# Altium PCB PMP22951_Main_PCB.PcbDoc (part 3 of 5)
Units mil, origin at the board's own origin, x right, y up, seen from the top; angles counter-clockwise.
Board outline 6643.5 x 4153.54 mil, 6 copper layers (Top Layer, Signal Layer 1, Signal Layer 2, Signal Layer 3, Signal Layer 4, Bottom Layer), stack 65.8 mil thick; 139 components, 80 nets, 687 pads, 417 vias.
Unrouted connection lines stored in the file: 2.
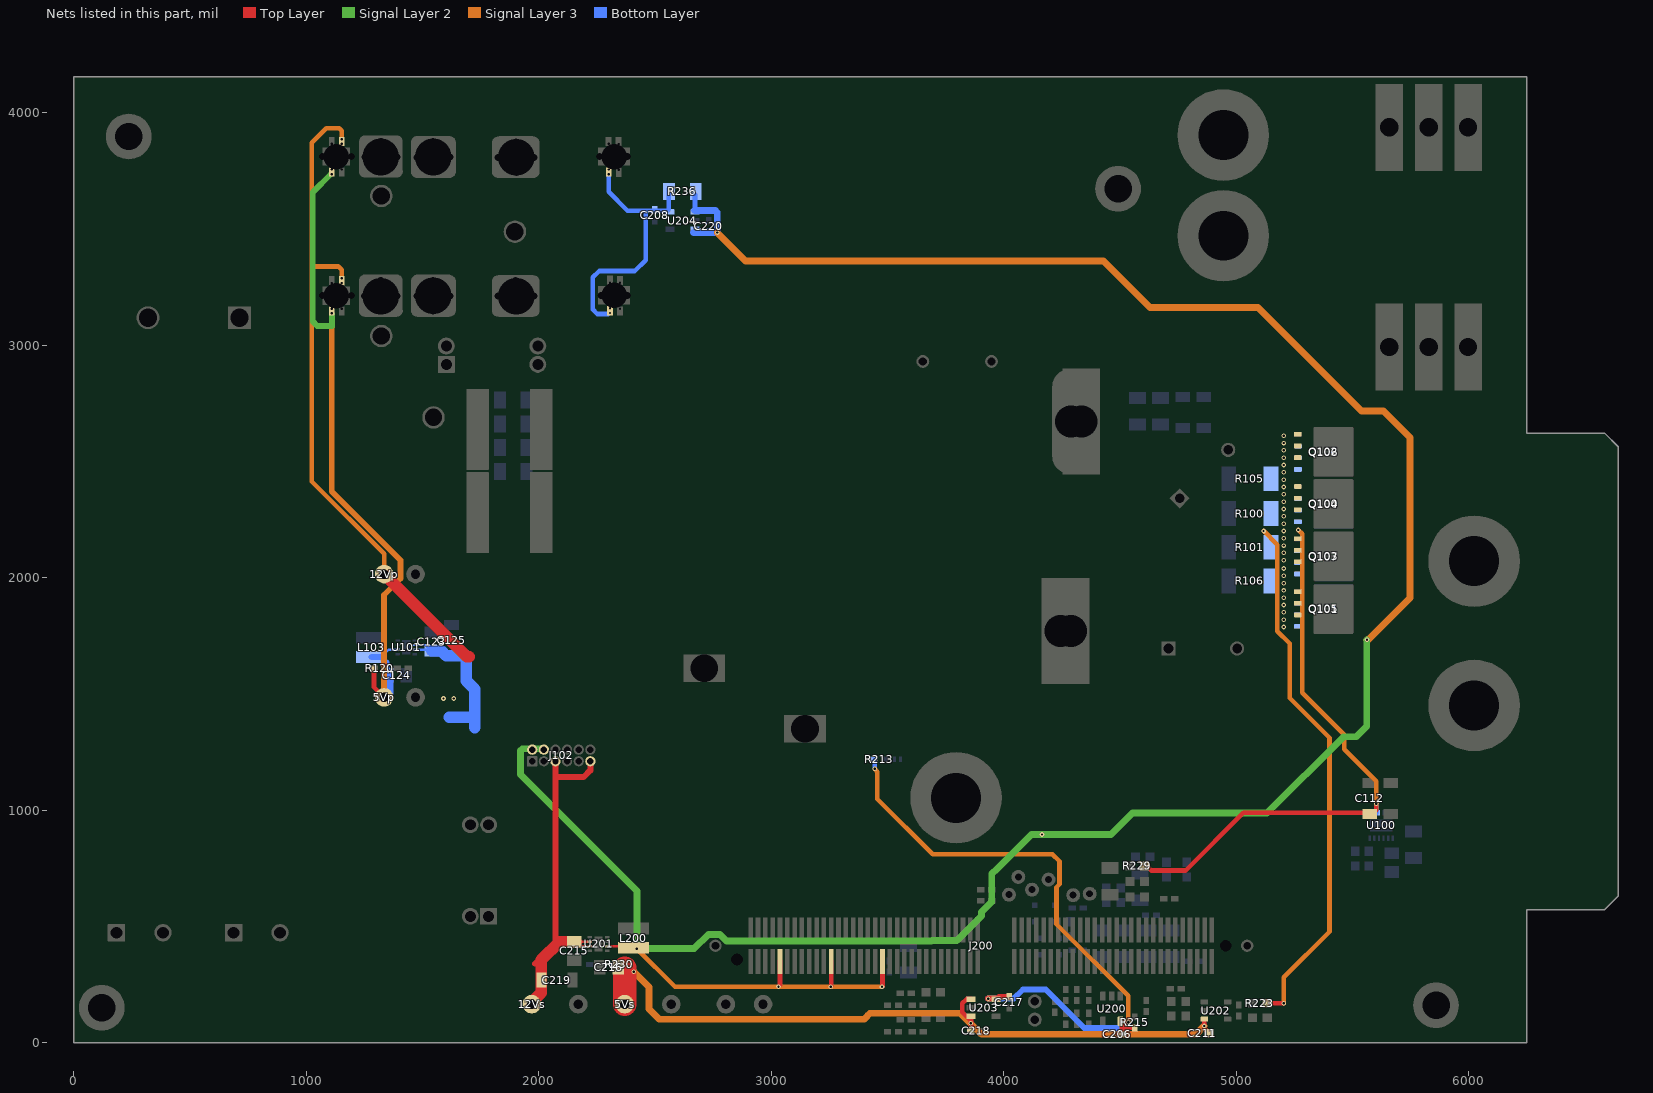
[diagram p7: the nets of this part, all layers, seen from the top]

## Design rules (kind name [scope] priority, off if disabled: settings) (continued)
SilkToSilkClearance SilkToSilkClearance_Pb-FreeLogo [(HasFootprint('Pb-Free_Overlay_Medium') OR HasFootprint('Pb-Free_Overlay_Small')) vs (HasFootprint('Pb-Free_Overlay_Medium') OR HasFootprint('Pb-Free_Overlay_Small'))] p1: silktosilkclearance=0
SilkToSilkClearance [All] p2: silktosilkclearance=4
SilkToSolderMaskClearance SilkToComponentPadClearance [(IsPad or IsFill or IsRegion) and InAnycomponent] p1: minsilkscreentomaskgap=5 clearancetoexposedcopper=TRUE
SilkToSolderMaskClearance "Silk to Solder Mask Opening" [All] p2: minsilkscreentomaskgap=4 clearancetoexposedcopper=FALSE
SolderMaskExpansion [All] p1: expansion=1.97
Width [All] p1: maxlimit=100 minlimit=6 preferedwidth=10 checkconnectedcopper=TRUE
13 further rules are at their usual default settings.

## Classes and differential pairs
component class PMP22951_Main_PSFB: 5Vp 12Vp C100 C101 C102 C103 C104 C105 C106 C110 C111 C112 C113 C114 C115 C116 C117 C118 C123 C124 C125 C224 C226 C242 C243 C244 CT100 CT101 CT200 J102 L100 L103 LOGO100 LOGO101 Logo102 Logo103 PGND Q100 Q101 Q102 Q103 Q104 Q105 Q106 Q107 Q215 Q216 Q217 Q218 Q219 R100 R101 R102 R103 R104 R105 R106 R107 R108 R116 R120 R121 SGND TP100 TP108 TP109 TP110 TP217 TP218 TP219 TP220 TP221 TP222 U100 U101 Vin Vout+ Vout-
component class PMP22951_Main_Controller: 5Vs 12Vs C200 C201 C202 C203 C204 C205 C206 C207 C208 C209 C210 C211 C212 C213 C214 C215 C216 C217 C218 C219 C220 C311 C333 D200 D201 D202 D203 J200 J300 J305 J306 L200 PSON R200 R201 R202 R203 R204 R205 R206 R207 R208 R209 R210 R211 R212 R213 R214 R215 R216 R217 R218 R219 R220 R221 R222 R223 R224 R225 R226 R227 R228 R229 R230 R231 R232 R233 R234 R235 R236 R305 R323 R329 R331 R333 R334 R335 R337 RT200 SGND U200 U201 U202 U203 U204
net class HV: NetT100_1 SWNODE2 VBB

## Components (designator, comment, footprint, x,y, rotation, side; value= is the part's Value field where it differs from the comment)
5Vp "5000" Keystone5000 1335,1485 r180 bottom
5Vs "5000" Keystone5000 2370,165 r90 top
12Vp "5000" Keystone5000 1335,2015 r180 bottom
12Vs "5000" Keystone5000 1970,165 r90 top
C100 "450HXG220MEFCSN25X40" HXG_2500x4000 515.75,3118.11 r180 top value=220uF
C101 "CL31B223KHHNNNE" 1206 1889.76,2763.78 r0 bottom value=0.022uF
C102 "CL31B223KHHNNNE" 1206 1889.76,2456.69 r0 bottom value=0.022uF
C103 "CL31B223KHHNNNE" 1206 1889.76,2559.06 r0 bottom value=0.022uF
C104 "CL31B223KHHNNNE" 1206 1889.76,2661.42 r0 bottom value=0.022uF
C105 "B58031U5105M062" FP-B58031U5105M062_SMD2-MFG 1874.02,2279.53 r180 top value=1µF
C106 "B58031U5105M062" FP-B58031U5105M062_SMD2-MFG 1874.02,2637.8 r180 top value=1µF
C110 "70RXA1000M18X25" HE_1800x2500 4856.5,1695 r0 top value=1000uF
C111 "70RXA1000M18X25" HE_1800x2500 4861.5,2445 r45 top value=1000uF
C112 "GCM31CR72A105KA03" 1206_180 5575,1050 r270 top value=1uF
C113 "GCM31CR72A105KA03" 1206_180 5665,1050 r90 top value=1uF
C114 "C0805C104K1RACTU" 0805_HV 5669.29,773.74 r90 bottom value=0.1uF
C115 "06033C104JAT2A" 0603 5570.87,791.34 r90 bottom value=0.1uF
C116 "DE6E3KJ222MN3A" E_900x700x900 3800,2930 r0 bottom value=2200pF
C117 "GCM31CR72A105KA03" 1206_180 4860,2710 r90 bottom value=1uF
C118 "GCM31CR72A105KA03" 1206_180 4770,2710 r90 bottom value=1uF
C123 "C0805C105K3RACTU" 0805_HV 1540,1725 r90 bottom value=1uF
C124 "CL21A226KQQNNNE" 0805_HV 1390,1580 r0 bottom value=22uF
C125 "GCM31CR71C106KA64L" 1206_180 1625,1730 r90 bottom value=10uF
C200 "GRM155R70J103KA01D" 0402 3578.74,98.43 r180 top value=0.01uF
C201 "GRM155R70J103KA01D" 0402 3578.74,212.6 r180 top value=0.01uF
C202 "885012205044" 0402 4712.6,618.11 r0 top value=1000pF
C203 "GRM155R70J103KA01D" 0402 3925.2,610.24 r0 top value=0.01uF
C204 "GRM1555C1H2R2BA01D" 0402 4366.14,102.36 r270 top value=2.2pF
C205 "CGA2B2X7R1H471K050BA" 0402 4820,350 r0 bottom value=470pF
C206 "0402YC104KAT2A" 0402 4488.19,35.43 r180 top value=0.1uF
C207 "CGA2B2X7R1H222K050BA" 0402 4267.72,204.72 r90 top value=2200pF
C208 "GRM155R70J104KA01D" 0402 2500,3559.06 r270 bottom value=0.1uF
C209 "0402YC104KAT2A" 0402 4314.96,204.72 r270 top value=0.1uF
C210 "06035A102KAT2A" 0603 4503.94,633.86 r90 bottom value=1000pF
C211 "C1608X7R1E105K080AB" 0603 4854.33,39.37 r0 top value=1uF
C212 "GRM1555C1E4R7CA01D" 0402 5011.81,137.8 r270 top value=4.7pF
C213 "0402YC101KAT2A" 0402 4740.16,232.28 r180 top value=100pF
C214 "06035A102KAT2A" 0603 4574.8,625.98 r0 top value=1000pF
C215 "C0805C105K3RACTU" 0805_HV 2152.17,393.94 r270 top value=1uF
C216 "CL21A226KQQNNNE" 0805_HV 2302.17,323.94 r180 top value=22uF
C217 "GRM155R70J104KA01D" 0402 4023.62,173.23 r270 top value=0.1uF
C218 "GRM155R70J104KA01D" 0402 3881.89,51.18 r0 top value=0.1uF
C219 "GCM31CR71C106KA64L" 1206_180 2078.31,268.78 r0 top value=10uF
C220 "GRM155R70J104KA01D" 0402 2732.28,3511.81 r90 bottom value=0.1uF
CT100 "PAS6282NL" FP-PAS6282NL_PTH_12MM5_4MM5-MFG 1745,740 r270 top value=3.3mH
CT101 "PAS6282NL" FP-PAS6282NL_PTH_12MM5_4MM5-MFG 1799.21,2956.69 r180 top value=3.3mH
D200 "BAS316,115" SOD-323 4177.17,590.55 r180 bottom value=100V
D201 "BAS316,115" SOD-323 4177.17,519.68 r180 bottom value=100V
D202 "BAS316,115" SOD-323 4196.85,377.95 r0 bottom value=100V
D203 "BAS316,115" SOD-323 4196.85,448.82 r0 bottom value=100V
J102 "M50-3000645" FP-M50-3000645_HDR12-MFG 2097.05,1235 r0 top locked
J200 "HSEC8-160-01-L-DV-A-BL" controlCARD-120HSEC 3976.38,417.32 r180 top
L100 "PAL6431.392NL" FP-PAL6567.421NL_PTH_IND_34MM0_9MM5-MFG 4289.06,2221.06 r90 top value=3.9µH
L103 "74438336022" FP-74438336010_SMD2-MFG 1280,1700 r270 bottom
L200 "74438336022" FP-74438336010_SMD2-MFG 2407.17,448.94 r270 top
LOGO100 "CAUTION HOT SURFACE" IEC_HotSurface_Small 735,865 r0 top
LOGO101 "DANGER HIGH VOLTAGE" IEC_HighVoltage_Small 445,860 r0 top
Logo102 "FCC disclaimer" FCC_disclaimer 7751.97,7307.09 r90 top
Logo103 "WEEE logo" WEEE_Minimum 175,885 r0 top
PGND "5001" Keystone5001 1470,2015 r90 bottom
PGND "5001" Keystone5001 1470,1485 r90 bottom
PGND "1715721" PhoenixContact_1715721 283.46,472.44 r0 top
PSON "5003" Keystone5003 2805,165 r90 top
Q100 "CSD19502Q5B" DNK0008A#1 5375.98,2316.93 r0 top value=80V
Q101 "CSD19502Q5B" DNK0008A#1 5375.98,1864.17 r0 top value=80V
Q102 "CSD19502Q5B" DNK0008A#1 5375.98,2541.34 r0 top value=80V
Q103 "CSD19502Q5B" DNK0008A#1 5375.98,2092.52 r0 top value=80V
Q104 "CSD19502Q5B" DNK0008A#2 5376.97,2315.32 r0 bottom value=80V
Q105 "CSD19502Q5B" DNK0008A#2 5376.97,1865.32 r0 bottom value=80V
Q106 "CSD19502Q5B" DNK0008A#2 5376.97,2540.32 r0 bottom value=80V
Q107 "CSD19502Q5B" DNK0008A#2 5376.97,2090.32 r0 bottom value=80V
R100 "PMR50HZPFV2L00" 2010 5059.33,2275.63 r0 bottom value=0.002
R101 "PMR50HZPFV2L00" 2010 5059.33,2130.63 r0 bottom value=0.002
R102 "CRCW0603243RFKEA" 0603 4700.79,744.09 r270 bottom value=243
R103 "RC1206FR-079K76L" 1206 4675,2715 r270 bottom value=9.76k
R104 "RC1206FR-079K76L" 1206 4575,2715 r270 bottom value=9.76k
R105 "PMR50HZPFV2L00" 2010 5059.33,2425.63 r0 bottom value=0.002
R106 "PMR50HZPFV2L00" 2010 5059.33,1985.63 r0 bottom value=0.002
R107 "CRCW0603243RFKEA" 0603 4787.4,744.09 r270 bottom value=243
R108 "CRCW120647R0JNEA" 1206 5763.78,850.39 r90 bottom value=47
R116 "CRCW06030000Z0EA" 0603 5511.81,791.34 r270 bottom value=0
R120 "CRCW0402681KFKED" 0402 1315,1610 r180 top value=681k
R121 "CRCW0402130KFKED" 0402 1415,1610 r180 top value=130k
R200 "CRCW04024K99FKED" 0402 3629.92,47.24 r0 top value=4.99k
R201 "CRCW0603100RFKEA" 0603 3696.85,106.3 r180 top value=100
R202 "CRCW04029K31FKED" 0402 3523.62,47.24 r0 top value=9.31k
R203 "CRCW04024K99FKED" 0402 3629.92,161.42 r0 top value=4.99k
R204 "CRCW0603100RFKEA" 0603 3696.85,216.54 r180 top value=100
R205 "CRCW04020000Z0ED" 0402 4633.86,547.24 r0 bottom value=0
R206 "CRCW04020000Z0ED" 0402 4318.9,578.74 r0 bottom value=0
R207 "CRCW04029K31FKED" 0402 3523.62,161.42 r0 top value=9.31k
R208 "CRCW120614R7FKEA" 1206 4520,425 r90 bottom value=14.7
R209 "CRCW120614R7FKEA" 1206 4420,425 r90 bottom value=14.7
R210 "RC0603FR-079K76L" 0603 4287.4,488.19 r270 bottom value=9.76k
R211 "CRCW04021K40FKED" 0402 3925.2,657.48 r180 top value=1.40k
R212 "CRCW04020000Z0ED" 0402 4318.9,397.64 r0 bottom value=0
R213 "CRCW040210K0FKED" 0402 3464.92,1218.62 r0 bottom value=10.0k
R214 "CRCW04023K65FKED" 0402 4314.96,102.36 r90 top value=3.65k
R215 "CRCW040210K0FKED" 0402 4562.99,86.61 r270 top value=10.0k
R216 "CRCW04021K00FKED" 0402 4267.72,102.36 r270 top value=1.00k
R217 "CRCW04021K00FKED" 0402 4220.47,153.54 r270 top value=1.00k
R218 "RC0402FR-0756R2L" 0402 4614.17,157.48 r90 top value=56.2
R219 "CRCW040210K0FKED" 0402 4366.14,204.72 r90 top value=10.0k
R220 "CRCW120637K4FKEA" 1206 4586.61,669.29 r90 bottom value=37.4k
R221 "CRCW0603100RFKEA" 0603 4598.43,799.21 r0 bottom value=100
R222 "RC0603FR-071K82L" 0603 4440.94,633.86 r270 bottom value=1.82k
R223 "RC0603FR-074R75L" 0603 5102.36,169.29 r180 top value=4.75
R224 "RC0603FR-0724KL" 0603 4783.46,145.67 r270 top value=24.0k
R225 "CRCW120610K0FKEA" 1206 3590.55,358.27 r270 bottom value=10.0k
R226 "RC0603FR-074R75L" 0603 5102.36,106.3 r180 top value=4.75
R227 "CRCW0603100KFKEA" 0603 4720.47,145.67 r90 top value=100k
R228 "CRCW120637K4FKEA" 1206 4456.69,692.91 r90 top value=37.4k
R229 "CRCW0603100RFKEA" 0603 4574.8,759.84 r0 top value=100
R230 "CRCW0402681KFKED" 0402 2346.02,335.71 r0 bottom value=681k
R231 "RC0603FR-071K82L" 0603 4574.8,692.91 r180 top value=1.82k
R232 "CRCW0402130KFKED" 0402 2243.66,335.71 r0 bottom value=130k
R233 "CRCW04021K00FKED" 0402 3507.87,326.77 r270 bottom value=1.00k
R234 "CRCW120614R7FKEA" 1206 4620,425 r90 bottom value=14.7
R235 "CRCW120614R7FKEA" 1206 4720,425 r90 bottom value=14.7
R236 "CRCW12060000Z0EA" 1206 2618.11,3661.42 r180 bottom value=0
RT200 "TMP6131DECR" DEC0002A 3543.66,1218.62 r180 bottom
SGND "5001" Keystone5001 2965,165 r90 top
SGND "5001" Keystone5001 2170,165 r90 top
SGND "5001" Keystone5001 2570,165 r90 top
SGND "575-4" Keystone_575-4 3795,1052.68 r0 top
TP100 "Suggest using a net name here" Mill-Max_0312-0-15-15-34-27-10-0 1322.83,3039.37 r0 top
TP108 "Suggest using a net name here" Mill-Max_0312-0-15-15-34-27-10-0 1322.83,3641.73 r0 top
TP109 "Suggest using a net name here" Mill-Max_0312-0-15-15-34-27-10-0 1547.24,2688.98 r0 top
TP110 "Suggest using a net name here" Mill-Max_0312-0-15-15-34-27-10-0 1897.64,3488.19 r0 top
U100 "LM74800QDRRRQ1" DRR0012E 5624.29,933.74 r270 bottom
U101 "TPS62160QDSGRQ1" DSG0008A#1 1430,1700 r180 bottom
U200 "LMV116MF/NOPB" DBV0005A_N 4464.57,145.67 r270 top
U201 "TPS62160QDSGRQ1" DSG0008A#2 2257.17,423.94 r0 top
U202 "INA293B3IDBVR" DBV0005A_L 4913.39,137.8 r0 top
U203 "TLV71333PQDBVRQ1" DBV0005A_N 3913.39,149.61 r0 top
U204 "TLV71333PQDBVRQ1" DBV0005A_N 2618.11,3535.43 r180 bottom
Vin "1715721" PhoenixContact_1715721 787.4,472.44 r0 top
Vout+ "575-4" Keystone_575-4 6023.62,2070.87 r0 top
Vout- "575-4" Keystone_575-4 6023.62,1450 r0 top

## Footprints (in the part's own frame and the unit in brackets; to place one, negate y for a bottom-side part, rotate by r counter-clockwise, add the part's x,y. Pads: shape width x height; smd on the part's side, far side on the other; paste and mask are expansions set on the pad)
0402 [mm] "0402 from SM-752 data"
  rect 0.8x0.6 smd: 1(-0.6,0) 2(0.6,0)
  silkscreen extent -1.22,-0.52 1.22,0.52, body extent -0.55,-0.3 0.55,0.3, height 0.6
0603 [mm] "0603 from SM-752 data"
  rect 1x0.95 smd: 1(-0.8,0) 2(0.8,0)
  silkscreen extent -1.52,-0.69 1.52,0.69, body extent -0.87,-0.47 0.87,0.47, height 1
0805_HV [mil] "0805 with 30mil clearance between pads"
  rect 50x63 smd: 1(-40,0) 2(40,0)
  silkscreen extent -74,-40 74,40, body extent -43,-29 43,29, height 57
1206 [mm] "1206 from SM-752 data"
  rect 1.3x1.85 smd: 1(-1.45,0) 2(1.45,0)
  silkscreen extent -2.4,-1.21 2.4,1.21, body extent -1.7,-0.9 1.7,0.9, height 1.35
1206_180 [mm] "1206_180"
  rect 1.1x1.6 smd: 1(-1.7,0) 2(1.7,0)
  silkscreen extent -0.9,-1 0.9,1, body extent -1.75,-0.95 1.75,0.95, height 1.8
2010 [mm] "Chip Capacitor, Body 5.08x2.54mm, IPC Medium Density"
  rect 1.6x2.7 smd: 1(-2.3,0) 2(2.3,0)
  silkscreen extent -3.42,-1.65 3.42,1.65, body extent -2.73,-1.45 2.73,1.45, height 1.66
controlCARD-120HSEC [mm] "Pads are not numbered according to Samtec datasheet."
  rect 0.5x2.724 smd: 1(-23.357,-1.678) 2(-23.357,1.722) 3(-22.557,-1.678) 4(-22.557,1.722) 5(-21.757,-1.678) 6(-21.757,1.722) 7(-20.957,-1.678) 8(-20.957,1.722) 9(-20.157,-1.678) 10(-20.157,1.722) 11(-19.357,-1.678) 12(-19.357,1.722) 13(-18.557,-1.678) 14(-18.557,1.722) 15(-17.757,-1.678) 16(-17.757,1.722) 17(-16.957,-1.678) 18(-16.957,1.722) 19(-16.157,-1.678) 20(-16.157,1.722) 21(-15.357,-1.678) 22(-15.357,1.722) 23(-14.557,-1.678) 24(-14.557,1.722) 25(-13.757,-1.678) 26(-13.757,1.722) 27(-12.957,-1.678) 28(-12.957,1.722) 29(-12.157,-1.678) 30(-12.157,1.722) 31(-11.357,-1.678) 32(-11.357,1.722) 33(-10.557,-1.678) 34(-10.557,1.722) 35(-9.757,-1.678) 36(-9.757,1.722) 37(-8.957,-1.678) 38(-8.957,1.722) 39(-8.157,-1.678) 40(-8.157,1.722) 41(-7.357,-1.678) 42(-7.357,1.722) 43(-6.557,-1.678) 44(-6.557,1.722) 45(-5.757,-1.678) 46(-5.757,1.722) 47(-4.957,-1.678) 48(-4.957,1.722) 49(-4.157,-1.678) 50(-4.157,1.722) 51(-3.357,-1.678) 52(-3.357,1.722) 53(-2.557,-1.678) 54(-2.557,1.722) 55(-1.757,-1.678) 56(-1.757,1.722) 57(2.243,-1.678) 58(2.243,1.722) 59(3.043,-1.678) 60(3.043,1.722) 61(3.843,-1.678) 62(3.843,1.722) 63(4.643,-1.678) 64(4.643,1.722) 65(5.443,-1.678) 66(5.443,1.722) 67(6.243,-1.678) 68(6.243,1.722) 69(7.043,-1.678) 70(7.043,1.722) 71(7.843,-1.678) 72(7.843,1.722) 73(8.643,-1.678) 74(8.643,1.722) 75(9.443,-1.678) 76(9.443,1.722) 77(10.243,-1.678) 78(10.243,1.722) 79(11.043,-1.678) 80(11.043,1.722) 81(11.843,-1.678) 82(11.843,1.722) 83(12.643,-1.678) 84(12.643,1.722) 85(13.443,-1.678) 86(13.443,1.722) 87(14.243,-1.678) 88(14.243,1.722) 89(15.043,-1.678) 90(15.043,1.722) 91(15.843,-1.678) 92(15.843,1.722) 93(16.643,-1.678) 94(16.643,1.722) 95(17.443,-1.678) 96(17.443,1.722) 97(18.243,-1.678) 98(18.243,1.722) 99(19.043,-1.678) 100(19.043,1.722) 101(19.843,-1.678) 102(19.843,1.722) 103(20.643,-1.678) 104(20.643,1.722) 105(21.443,-1.678) 106(21.443,1.722) 107(22.243,-1.678) 108(22.243,1.722) 109(23.043,-1.678) 110(23.043,1.722) 111(23.843,-1.678) 112(23.843,1.722) 113(24.643,-1.678) 114(24.643,1.722) 115(25.443,-1.678) 116(25.443,1.722) 117(26.243,-1.678) 118(26.243,1.722) 119(27.043,-1.678) 120(27.043,1.722)
  round 0.025 hole 1.27 unplated mask+0.876: 181(-24.857,0.022) 182(28.543,1.522)
  round 1.348 hole 0.84: 185(-27.207,0.022) 186(30.893,0.022)
  silkscreen extent -32.11,-3.86 35.8,3.9, body extent -31.75,-3.48 35.3,3.52, height 12.35
DBV0005A_L [mm] "SOT23, 5-Leads, Body 2.9x1.6mm, Pitch 0.95mm, Lead Span 2.8mm, IPC High Density"
  rrect18% 0.8x0.55 smd: 1(-1.275,0.95) 2(-1.275,0) 3(-1.275,-0.95) 4(1.275,-0.95) 5(1.275,0.95)
  silkscreen extent -1.63,-1.55 0.38,1.55, body extent -1.42,-1.46 1.42,1.46, height 1.09
DBV0005A_N [mm] "SOT23, 5-Leads, Body 2.9x1.6mm, Pitch 0.95mm, Lead Span 2.8mm, IPC Medium Density"
  rrect17% 1x0.6 smd: 1(-1.375,0.95) 2(-1.375,0) 3(-1.375,-0.95) 4(1.375,-0.95) 5(1.375,0.95)
  silkscreen extent -1.63,-1.55 0.38,1.55, body extent -1.42,-1.46 1.42,1.46, height 1.09
DEC0002A [mm] "X1SON-2"
  rrect57% 0.35x0.6 smd paste-0.5 mask-0.05: 1(-0.325,0) 2(0.325,0)
  rrect33% 0.3x0.5 on Bottom Paste: 1S(-0.35,0) 2S(0.35,0)
  body extent -0.5,-0.3 0.5,0.3, height 0.5
DNK0008A#1 [mm] "SON, 8-Leads, Body 5x6mm"
  rrect39% 0.86x0.51 smd paste-0.05 mask-0.05: 1(-2.82,1.905) 2(-2.82,0.635) 3(-2.82,-0.635) 4(-2.82,-1.905) 5(2.82,-1.905) 6(2.82,-0.635) 7(2.82,0.635) 8(2.82,1.905)
  rrect40% 0.25x0.555 on Top Paste: 9(-0.83,-2.372) 9(-0.83,2.372)
  rrect40% 0.25x0.555 on Top Solder: 9(-0.83,-2.372) 9(-0.83,2.372)
  rrect11% 0.95x1.13 on Top Paste: 9(-0.535,-1.33) 9(-0.535,0) 9(-0.535,1.33) 9(0.615,-1.33) 9(0.615,0) 9(0.615,1.33) 9(1.765,-1.33) 9(1.765,0) 9(1.765,1.33)
  rrect3% 3.58x4 on Top Solder: 9(0.75,0)
  rrect5% 4.34x5.4 smd paste-3 mask-3: 9(1.08,0)
  body extent -3.05,-2.55 3.05,2.55, height 1.06
DNK0008A#2 [mm] "SON, 8-Leads, Body 5x6mm"
  rrect39% 0.86x0.51 smd paste-0.05 mask-0.05: 1(-2.82,1.905) 2(-2.82,0.635) 3(-2.82,-0.635) 4(-2.82,-1.905) 5(2.82,-1.905) 6(2.82,-0.635) 7(2.82,0.635) 8(2.82,1.905)
  rrect40% 0.25x0.555 on Bottom Paste: 9(-0.83,-2.372) 9(-0.83,2.372)
  rrect40% 0.25x0.555 on Bottom Solder: 9(-0.83,-2.372) 9(-0.83,2.372)
  rrect11% 0.95x1.13 on Bottom Paste: 9(-0.535,-1.33) 9(-0.535,0) 9(-0.535,1.33) 9(0.615,-1.33) 9(0.615,0) 9(0.615,1.33) 9(1.765,-1.33) 9(1.765,0) 9(1.765,1.33)
  rrect3% 3.58x4 on Bottom Solder: 9(0.75,0)
  rrect5% 4.34x5.4 smd paste-3 mask-3: 9(1.08,0)
  body extent -3.05,-2.55 3.05,2.55, height 1.06
DRR0012E [mm] "WSON-12"
  rrect40% 0.62x0.25 smd: 1(-1.39,1.25) 2(-1.39,0.75) 3(-1.39,0.25) 4(-1.39,-0.25) 5(-1.39,-0.75) 6(-1.39,-1.25) 7(1.39,-1.25) 8(1.39,-0.75) 9(1.39,-0.25) 10(1.39,0.25) 11(1.39,0.75) 12(1.39,1.25)
  rrect8% 1.3x2.5 smd paste-1.7: 13(0,0)
  silkscreen extent -2,-1.8 2,1.8, body extent -1.5,-1.5 1.5,1.5, height 0.81
DSG0008A#1 [mm] "SON, 8-Leads, Body 2x2mm, Pitch 0.5mm, Thermal Pad 1.6x0.9mm, TI Recommended"
  rrect40% 0.5x0.25 smd: 1(-0.95,0.75) 2(-0.95,0.25) 3(-0.95,-0.25) 4(-0.95,-0.75) 5(0.95,-0.75) 6(0.95,-0.25) 7(0.95,0.25) 8(0.95,0.75)
  rrect14% 0.9x0.7 on Bottom Paste: 9(0,-0.45) 9(0,0.45)
  rrect11% 0.9x1.6 smd paste-0.45: 9(0,0)
  silkscreen extent -1.07,-1.15 1.07,1.15, body extent -1,-1 1,1, height 0.77
DSG0008A#2 [mm] "SON, 8-Leads, Body 2x2mm, Pitch 0.5mm, Thermal Pad 1.6x0.9mm, TI Recommended"
  rrect40% 0.5x0.25 smd: 1(-0.95,0.75) 2(-0.95,0.25) 3(-0.95,-0.25) 4(-0.95,-0.75) 5(0.95,-0.75) 6(0.95,-0.25) 7(0.95,0.25) 8(0.95,0.75)
  rrect14% 0.9x0.7 on Top Paste: 9(0,-0.45) 9(0,0.45)
  rrect11% 0.9x1.6 smd paste-0.45: 9(0,0)
  silkscreen extent -1.07,-1.15 1.07,1.15, body extent -1,-1 1,1, height 0.77
E_900x700x900 [mm] "TH, 2- Leads, Body 9x7mm, Pin Spacing 7.5mm"
  round 1.4 hole 0.9: 1(-3.75,0) 2(3.75,0)
  silkscreen extent -4.5,-3.5 4.5,3.5, body extent -4.5,-3.5 4.5,3.5, height 12
FCC_disclaimer [mil]
FP-74438336010_SMD2-MFG [mm]
  rrect8% 1.3x3.4 smd paste+0 mask+0: 1(-1.05,0) 2(1.05,0)
  silkscreen extent -1.6,-2.1 1.6,2.1, body extent -1.5,-1.5 1.5,1.5, height 2
FP-B58031U5105M062_SMD2-MFG [mm]
  rrect4% 2.45x8.85 smd paste+0 mask+0: 1(-3.475,0) 2(3.475,0)
  silkscreen extent -1.88,-4.18 1.88,4.18, body extent -4.8,-4.52 4.8,4.52, height 0.25
FP-M50-3000645_HDR12-MFG [mm]
  rrect9% 1.12x1.12 hole 0.7 paste-1000 mask+0: 1(-3.175,-0.635)
  round 1.12 hole 0.7 paste-1000 mask+0: 2(-3.175,0.635) 3(-1.905,-0.635) 4(-1.905,0.635) 5(-0.635,-0.635) 6(-0.635,0.635) 7(0.635,-0.635) 8(0.635,0.635) 9(1.905,-0.635) 10(1.905,0.635) 11(3.175,-0.635) 12(3.175,0.635)
  silkscreen extent -4.73,-1.63 4.16,1.63, body extent -4.26,-1.73 4.26,1.73, height 0.25
FP-PAL6567.421NL_PTH_IND_34MM0_9MM5-MFG [mm]
  rrect2% 11.6x4.1 hole 3.5 slot 11 at 0 deg paste-1000 mask+0: 1(-11.45,0)
  rrect100% 11.6x4.1 hole 3.5 slot 11 at 0 deg paste-1000 mask+0: 2(11.45,0)
  silkscreen extent -18.01,-4.75 17,4.75, body extent -17.35,-4.85 17.35,4.85, height 0.25
FP-PAS6282NL_PTH_12MM5_4MM5-MFG [mm]
  rrect5% 1.85x1.85 hole 1.2 paste-1000 mask+0: 1(5,1)
  round 1.85 hole 1.2 paste-1000 mask+0: 2(-5,1) 3(-5,-1) 4(5,-1)
  silkscreen extent -3.7,-2.25 5.12,2.88, body extent -6.35,-2.35 6.35,2.35, height 0.25
HE_1800x2500 [mm] "TH, 2-Leads, Dia 18mm, Pin Spacing 7.5mm"
  rect 1.55x1.55 hole 1.05: 1(-3.75,0)
  round 1.55 hole 1.05: 2(3.75,0)
  silkscreen extent -9.25,-9.25 9.25,9.25, body extent -9.25,-9.25 9.26,9.25, height 27.01
HXG_2500x4000 [mm] "TH, 2-Leads, Dia 25mm, Pin Spacing 10mm"
  rect 2.5x2.5 hole 2: 1(-5,0)
  round 2.5 hole 2: 2(5,0)
  silkscreen extent -13,-13 13,13, body extent -12.9,-12.97 13.1,12.97, height 42
IEC_HighVoltage_Small [mil]
  silkscreen extent -107,-88 107,97
IEC_HotSurface_Small [mil]
  silkscreen extent -107,-93 107,92
Keystone5000 [mil] "For Keystone 500x miniature loop terminals"
  round 80 hole 40: 1(0,0)
  silkscreen extent -52,-52 52,52, body extent -49,-49 49,49, height 182
Keystone5001 [mil] "For Keystone 500x miniature loop terminals"
  round 80 hole 40: 1(0,0)
  silkscreen extent -52,-52 52,52, body extent -49,-49 49,49, height 182
Keystone5003 [mil] "For Keystone 500x miniature loop terminals"
  round 80 hole 40: 1(0,0)
  silkscreen extent -52,-52 52,52, body extent -49,-49 49,49, height 182
Keystone_575-4 [mm] "Banana Jack"
  round 10 hole 5.45: 1(0,0)
  body extent -3.95,-3.95 3.92,3.93, height 2.36
Mill-Max_0312-0-15-15-34-27-10-0 [mm] "Pin Receptacle, .032-.046\" .075\" Dia, Gold, TH"
  round 2.45 hole 1.905: 1(0,0)
  silkscreen extent -1.52,-1.52 1.52,1.52, body extent -1.15,-1.15 1.16,1.15, height 0.46
PhoenixContact_1715721 [mm] "Phoenix Contact 1715721 used on LM3445 design from Longmont"
  rrect5% 1.905x1.905 hole 1.3: 1(-2.54,0)
  round 1.9 hole 1.3: 2(2.54,0)
  silkscreen extent -5.82,-5.25 5.08,5.2, body extent -5.82,-4.6 5.08,5.2, height 14.2
SOD-323 [mm] "NXP recommended land pattern"
  rect 0.6x0.6 smd paste-0.05: 1(-1.1,0) 2(1.1,0)
  silkscreen extent -2.06,-0.86 1.53,0.86, body extent -1.3,-0.67 1.3,0.68, height 1.1
WEEE_Minimum [mil] "WEEElie bin"
  silkscreen extent -95,-172 99,104

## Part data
5Vp 5Vs 12Vp 12Vs: "Test Point, Miniature, Red, TH", Color=Red, Manufacturer=Keystone, Supplier Part Number 1=36-5000-ND
C100: "CAP, AL, 220 µF, 450 V, +/- 20%, TH", Cap_Case=25x40mm, Manufacturer=Rubycon, Supplier Part Number 1=1189-1974-ND, Tolerance_%=20, Value2=450V, ValueDisplayed=220µF
C101 C102 C103 C104: library part VJ1206Y223KXGAT5Z, "CAP, CERM, 0.022 µF, 630 V,+/- 10%, X7R, 1206", Cap_Case=1206, Manufacturer="Samsung Electro-Mechanics", TempCo=X7R, Tolerance_%=10, Value2=630V, ValueDisplayed=0.022µF
C105 C106: library part CMP-0091050-1, "TDK 1µF Multilayer Ceramic Capacitor MLCC 500V dc ±20% SMD", Digikey Part Number=495-75234-1-ND, Manufacturer=TDK, Mouser Part Number=871-B58031U5105M062, Operating Temperature Range="-40°C to +150°C", Tolerance_%=20%, ValueDisplayed=1uF
C110 C111: library part UHE1H122MHD6, "CAP, AL, 1000 µF, 70 V, +/- 20%, TH", Cap_Case=18x25mm, Manufacturer=Rubycon, Tolerance_%=20, Value2=70V, ValueDisplayed=1000µF
C112 C113 C117 C118: "CAP, CERM, 1 µF, 100 V,+/- 10%, X7R, AEC-Q200 Grade 1, 1206", Cap_Case=1206, Manufacturer=MuRata, Supplier Part Number 1=GCM31CR72A105KA03L-ND, TempCo=X7R, Tolerance_%=10, Value2=100V, ValueDisplayed=1µF
C114: "CAP, CERM, 0.1 µF, 100 V,+/- 10%, X7R, 0805", Cap_Case=0805, Manufacturer=Kemet, Supplier Part Number 1=399-3486-1-ND, TempCo=X7R, Tolerance_%=10, Value1="0.064 ohm", Value2=100V, ValueDisplayed=0.1µF
C115: "CAP, CERM, 0.1 µF, 25 V,+/- 5%, X7R, 0603", Cap_Case=0603, Manufacturer=AVX, Supplier Part Number 1=478-3713-1-ND, TempCo=X7R, Tolerance_%=5, Value1="0.05 ohm", Value2=25V, ValueDisplayed=0.1µF
C116: "CAP, CERM, 2200 pF, 300 V, +/- 20%, E, TH, 2- Leads, Body 9x7mm, Pin Spacing 7.5mm", Cap_Case=9x7x9mm, Manufacturer=MuRata, Supplier Part Number 1=DE6E3KJ222MN3A-ND, TempCo=E, Tolerance_%=20, Value1=Unknown, Value2=300V, ValueDisplayed=2200pF
C123 C215: library part CMP-0007728-2, "CAP, CERM, 1 uF, 25 V, +/- 10%, X7R, 0805", Cap_Case=0805, Manufacturer=Kemet, Supplier Part Number 1=399-8004-1-ND, TempCo=X7R, Tolerance_%=10%, Value1=Unknown, Value2=25V, ValueDisplayed=1uF
C124 C216: library part CMP-0007989-2, "CAP, CERM, 22 uF, 6.3 V, +/- 10%, X5R, 0805", Cap_Case=0805, Manufacturer="Samsung Electro-Mechanics", TempCo=X5R, Tolerance_%=10%, Value1=Unknown, Value2=6.3V, ValueDisplayed=22uF
C125 C219: "CAP, CERM, 10 µF, 16 V,+/- 10%, X7R, AEC-Q200 Grade 1, 1206", Cap_Case=1206, Manufacturer=MuRata, Supplier Part Number 1=490-4793-1-ND, TempCo=X7R, Tolerance_%=10, Value2=16V, ValueDisplayed=10µF
C200 C201 C203: "CAP, CERM, 0.01uF, 6.3V, +/-10%, X7R, 0402", Cap_Case=0402, Manufacturer=MuRata, Supplier Part Number 1=GRM155R70J103KA01D-ND, TempCo=X7R, Tolerance_%=10, Value1=Unknown, Value2=6.3V, ValueDisplayed=0.01uF
C202: "CAP, CERM, 1000 pF, 25 V,+/- 10%, X7R, 0402", Cap_Case=0402, Manufacturer="Wurth Elektronik", Supplier Part Number 1=710-885012205044, TempCo=X7R, Tolerance_%=10, Value2=25V, ValueDisplayed=1000pF
C204: "CAP, CERM, 2.2 pF, 50 V,+/- 5%, C0G/NP0, 0402", Cap_Case=0402, Manufacturer=MuRata, Supplier Part Number 1=490-6227-1-ND, TempCo=C0G/NP0, Tolerance_%=5, Value2=50V, ValueDisplayed=2.2pF
C205: library part CMP-0006320-2, "CAP, CERM, 470 pF, 50 V, +/- 10%, X7R, AEC-Q200 Grade 1, 0402", Cap_Case=0402, Manufacturer=TDK, Supplier Part Number 1=445-6888-1-ND, TempCo=X7R, Tolerance_%=10%, Value1="4.96489 ohm", Value2=50V, ValueDisplayed=470pF
C206 C209: "CAP, CERM, 0.1 µF, 16 V,+/- 10%, X7R, 0402", Cap_Case=0402, Manufacturer=AVX, Supplier Part Number 1=478-7888-1-ND, TempCo=X7R, Tolerance_%=10, Value2=16V, ValueDisplayed=0.1µF
C207: "CAP, CERM, 2200 pF, 50 V,+/- 10%, X7R, AEC-Q200 Grade 1, 0402", Cap_Case=0402, Manufacturer=TDK, Supplier Part Number 1=445-5606-1-ND, TempCo=X7R, Tolerance_%=10, Value1="1.07794 ohm", Value2=50V, ValueDisplayed=2200pF
C208 C217 C218 C220: "CAP, CERM, 0.1uF, 6.3V, +/-10%, X7R, 0402", Cap_Case=0402, Manufacturer=MuRata, Supplier Part Number 1=GRM155R70J104KA01D-ND, TempCo=X7R, Tolerance_%=10, Value1=Unknown, Value2=6.3V, ValueDisplayed=0.1uF
C210 C214: "CAP, CERM, 1000pF, 50V, +/-10%, C0G/NP0, 0603", Cap_Case=0603, Manufacturer=AVX, Supplier Part Number 1=478-3718-1-ND, TempCo=C0G/NP0, Tolerance_%=10, Value1="0.048 ohm", Value2=50V, ValueDisplayed=1000pF
C211: "CAP, CERM, 1uF, 25V, +/-10%, X7R, 0603", Cap_Case=0603, Manufacturer=TDK, Supplier Part Number 1=445-5956-1-ND, TempCo=X7R, Tolerance_%=10, Value1=Unknown, Value2=25V, ValueDisplayed=1uF
C212: "CAP, CERM, 4.7 pF, 25 V,+/- 5%, C0G/NP0, 0402", Cap_Case=0402, Manufacturer=MuRata, Supplier Part Number 1=81-GRM1555C1E4R7CA1D, TempCo=C0G/NP0, Tolerance_%=5, Value2=25V, ValueDisplayed=4.7pF
C213: "CAP, CERM, 100 pF, 16 V,+/- 10%, X7R, 0402", Cap_Case=0402, Manufacturer=AVX, Supplier Part Number 1=478-7887-1-ND, TempCo=X7R, Tolerance_%=10, Value2=16V, ValueDisplayed=100pF
CT100 CT101: library part CMP-0091119-1, "Inductor PTH 3.3mH 300mOhm", Manufacturer="Pulse Electronics", Operating Temperature Range="-40°C to +125°C", Test Frequency=100kHz
D200 D201 D202 D203: "Diode, Ultrafast, 100 V, 0.25 A, SOD-323", Manufacturer=Nexperia, Supplier Part Number 1=568-5003-1-ND, Value1=0.25A, Value2=1.4V
J102: library part CMP-0094055-1, "12 Position Receptacle Connector 0.050\" (1.27mm) Through Hole Gold", Current_A=1A, Digikey Part Number=952-1366-5-ND, Manufacturer=Harwin, Mouser Part Number=855-M50-3000645, Operating Temperature Range="-40°C to +105°C"
J200: library part controlCARD-120HSEC, "C2000 controlCARD-120HSEC connector, SMT", Manufacturer=Samtec
L100: library part CMP-0093530-1, "INDUCTOR, POWER, EP33, TH 0.42uH 20% 10kHz 0.06mOhm DCR MAX 300A Isat", Manufacturer=Pulse, Operating Temperature Range="-40°C to +125°C", Test Frequency=10kHz, Tolerance_%=20%
L103 L200: library part CMP-0087867-1, "2.2µH Shielded Molded Inductor 2.4A 67mOhm Max 2-SMD", Manufacturer="Wurth Electronics"
LOGO100: library part CMP-0074837-1, "IEC 61010-1 Hot Surface Warning"
LOGO101: library part CMP-0074835-1, "IEC 61010-1 High Voltage Warning"
Logo102: library part CMP-0074847-1, "FCC_disclaimer"
Logo103: library part CMP-0074769-1
PGND PGND SGND SGND SGND: "Test Point, Miniature, Black, TH", Color=Black, Manufacturer=Keystone, Supplier Part Number 1=36-5001-ND
PGND Vin: library part CMP-0055471-1, "Terminal Block, 5.08 mm, 2x1, TH", Color=Green, Current_A=17.5A, Manufacturer="Phoenix Contact", Supplier Part Number 1=277-1263-ND, Voltage_V=400V
PSON: "Test Point, Miniature, Orange, TH", Color=Orange, Manufacturer=Keystone, Supplier Part Number 1=36-5003-ND
Q100 Q101 Q102 Q103 Q104 Q105 Q106 Q107: library part CMP-0000915-2, "MOSFET, N-CH, 80 V, 100 A, DNK0008A (VSON-CLIP-8)", Alternate Manufacturer=None, Manufacturer="Texas Instruments", Supplier Part Number 1=296-37194-1-ND, Value2="48 nC"
R100 R101 R105 R106: "RES, 0.002, 1%, 1 W, 2010", Manufacturer=Rohm, Power_W=1, Supplier Part Number 1=RHM.002ASCT-ND, TempCo="100 ppm/C", Value1=1%, Value2=1W, Value_Code=2L000, ValueDisplayed=0.002
R102 R107: "RES, 243, 1%, 0.1 W, 0603", Manufacturer=Vishay-Dale, Power_W=0.1, Supplier Part Number 1=541-243HCT-ND, TempCo="100 ppm/C", Tolerance_%=1, Value1=1%, Value2=0.1W, Value_Code=243R, ValueDisplayed=243
R103 R104: "RES, 9.76 k, 1%, 0.25 W, 1206", Manufacturer="Yageo America", Power_W=0.25, Supplier Part Number 1=311-9.76KFRCT-ND, TempCo="100 ppm/C", Tolerance_%=1, Value1=1%, Value2=0.25W, Value_Code=9k76, ValueDisplayed=9.76k
R108: "RES, 47, 5%, 0.25 W, 1206", Manufacturer=Vishay-Dale, Power_W=0.25, Supplier Part Number 1=541-47ECT-ND, TempCo="200 ppm/C", Tolerance_%=5, Value1=5%, Value2=0.25W, Value_Code=47R0, ValueDisplayed=47
R116: "RES, 0, 5%, 0.1 W, 0603", Manufacturer=Vishay-Dale, Power_W=0.1, Supplier Part Number 1=541-0.0GCT-ND, TempCo="200 ppm/C", Tolerance_%=5, Value1=5%, Value2=0.1W, Value_Code=0000, ValueDisplayed=0
R120 R230: library part CMP-0026504-2, "RES, 681 k, 1%, 0.063 W, AEC-Q200 Grade 0, 0402", Manufacturer=Vishay-Dale, Power_W=63mW, Supplier Part Number 1=541-681KLCT-ND, TempCo="100 ppm/C", Tolerance_%=1%, Value2=0.063W, Value_Code=681k
R121 R232: library part CMP-0025997-3, "RES, 130 k, 1%, 0.063 W, AEC-Q200 Grade 0, 0402", Manufacturer=Vishay-Dale, Power_W=63mW, Supplier Part Number 1=541-130KLCT-ND, TempCo="100 ppm/C", Tolerance_%=1%, Value2=0.063W, Value_Code=130k
R200 R203: "RES, 4.99 k, 1%, 0.063 W, 0402", Manufacturer=Vishay-Dale, Power_W=0.063, Supplier Part Number 1=541-4.99KLCT-ND, TempCo="100 ppm/C", Tolerance_%=1, Value1=1%, Value2=0.063W, Value_Code=4k99, ValueDisplayed=4.99k
R201 R204 R221 R229: "RES, 100, 1%, 0.1 W, 0603", Manufacturer=Vishay-Dale, Power_W=0.1, Supplier Part Number 1=541-100HCT-ND, TempCo="100 ppm/C", Tolerance_%=1, Value1=1%, Value2=0.1W, Value_Code=100R, ValueDisplayed=100
R202 R207: "RES, 9.31 k, 1%, 0.063 W, 0402", Manufacturer=Vishay-Dale, Power_W=0.063, Supplier Part Number 1=541-9.31KLCT-ND, TempCo="100 ppm/C", Tolerance_%=1, Value1=1%, Value2=0.063W, Value_Code=9k31, ValueDisplayed=9.31k
R205 R206 R212: "RES, 0, 5%, 0.063 W, 0402", Manufacturer=Vishay-Dale, Power_W=0.063, Supplier Part Number 1=541-0.0JCT-ND, TempCo="200 ppm/C", Tolerance_%=5, Value1=5%, Value2=0.063W, Value_Code=0000, ValueDisplayed=0
R208 R209 R234 R235: "RES, 14.7, 1%, 0.25 W, 1206", Manufacturer=Vishay-Dale, Power_W=0.25, Supplier Part Number 1=541-14.7FCT-ND, TempCo="100 ppm/C", Tolerance_%=1, Value1=1%, Value2=0.25W, Value_Code=14R7, ValueDisplayed=14.7
R210: library part RC0603FR-079k76L, "RES, 9.76 k, 1%, 0.1 W, 0603", Manufacturer="Yageo America", Power_W=0.1, Supplier Part Number 1=311-9.76KHRCT-ND, TempCo="200 ppm/C", Tolerance_%=1, Value1=1%, Value2=0.1W, Value_Code=9k76, ValueDisplayed=9.76k
R211: "RES, 1.40k ohm, 1%, 0.063W, 0402", Manufacturer=Vishay-Dale, Power_W=0.063, Supplier Part Number 1=541-1.40KLCT-ND, TempCo="100 ppm/C", Tolerance_%=1, Value1=1%, Value2=0.063W, Value_Code=1k40
R213 R215 R219: "RES, 10.0 k, 1%, 0.063 W, 0402", Manufacturer=Vishay-Dale, Power_W=0.063, Supplier Part Number 1=541-10.0KLCT-ND, TempCo="100 ppm/C", Tolerance_%=1, Value1=1%, Value2=0.063W, Value_Code=10k0, ValueDisplayed=10.0k
R214: "RES, 3.65 k, 1%, 0.063 W, 0402", Manufacturer=Vishay-Dale, Power_W=0.063, Supplier Part Number 1=541-3.65KLCT-ND, TempCo="100 ppm/C", Tolerance_%=1, Value1=1%, Value2=0.063W, Value_Code=3k65, ValueDisplayed=3.65k
R216 R217 R233: "RES, 1.00 k, 1%, 0.063 W, 0402", Manufacturer=Vishay-Dale, Power_W=0.063, Supplier Part Number 1=541-1.00KLCT-ND, TempCo="100 ppm/C", Tolerance_%=1, Value1=1%, Value2=0.063W, Value_Code=1k00, ValueDisplayed=1.00k
R218: library part CRCW040256R2FKED, "RES SMD 56.2 OHM 1% 1/16W 0402", Manufacturer=Yageo, Power_W=0.063, TempCo="100 ppm/C", Tolerance_%=1, Value1=1%, Value2=0.063W, Value_Code=56R2, ValueDisplayed=56.2
R220 R228: "RES, 37.4 k, 1%, 0.25 W, 1206", Manufacturer=Vishay-Dale, Power_W=0.25, Supplier Part Number 1=541-37.4KFCT-ND, TempCo="100 ppm/C", Tolerance_%=1, Value1=1%, Value2=0.25W, Value_Code=37k4, ValueDisplayed=37.4k
R222 R231: "RES, 1.82 k, 1%, 0.1 W, 0603", Manufacturer="Yageo America", Power_W=0.1, Supplier Part Number 1=311-1.82KHRCT-ND, TempCo="200 ppm/C", Tolerance_%=1, Value1=1%, Value2=0.1W, Value_Code=1k82, ValueDisplayed=1.82k
R223 R226: "RES, 4.75, 1%, 0.1 W, 0603", Manufacturer="Yageo America", Power_W=0.1, Supplier Part Number 1=311-4.75HRCT-ND, TempCo="200 ppm/C", Tolerance_%=1, Value1=1%, Value2=0.1W, Value_Code=4R75, ValueDisplayed=4.75
R224: "RES, 24.0 k, 1%, 0.1 W, 0603", Manufacturer="Yageo America", Power_W=0.1, Supplier Part Number 1=311-24.0KHRCT-ND, TempCo="200 ppm/C", Tolerance_%=1, Value1=1%, Value2=0.1W, Value_Code=24k0, ValueDisplayed=24.0k
R225: "RES, 10.0 k, 1%, 0.25 W, 1206", Manufacturer=Vishay-Dale, Power_W=0.25, Supplier Part Number 1=541-10.0KFCT-ND, TempCo="100 ppm/C", Tolerance_%=1, Value1=1%, Value2=0.25W, Value_Code=10k0, ValueDisplayed=10.0k
R227: "RES, 100 k, 1%, 0.1 W, 0603", Manufacturer=Vishay-Dale, Power_W=0.1, Supplier Part Number 1=541-100KHCT-ND, TempCo="100 ppm/C", Tolerance_%=1, Value1=1%, Value2=0.1W, Value_Code=100k
R236: "RES, 0, 5%, 0.25 W, 1206", Manufacturer=Vishay-Dale, Power_W=0.25, Supplier Part Number 1=541-0.0ECT-ND, TempCo="200 ppm/C", Tolerance_%=5, Value1=5%, Value2=0.25W, Value_Code=0000, ValueDisplayed=0
RT200: library part CMP-0084566-1, "Thermistor, DEC0002A (X1SON-2)", Alternate Manufacturer="Texas Instruments", Alternate PartNumber=TMP6131DECT
SGND Vout+ Vout-: "Standard Banana Jack, Uninsulated, 5.5mm", Manufacturer=Keystone, Supplier Part Number 1=36-575-4-ND
TP100 TP108 TP109 TP110: library part 0312-0-15-15-34-27-10-0, "Pin Receptacle, .032-.046\" .075\" Dia, Gold, TH", Manufacturer=Mill-Max, Supplier Part Number 1=0312-015153427100-ND
U100: library part CMP-0860988-1, "Ideal Diode Controller with Load Dump Protection, DRR0012E (WSON-12)", Alternate Manufacturer="Texas Instruments"
U101 U201: library part CMP-0067100-2, "3V-17V 1A Automotive Step-Down Converters in 2x2SON, DSG0008A (WSON-8)", Alternate Manufacturer="Texas Instruments", Alternate PartNumber=TPS62160QDSGTQ1
U200: library part CMP-0068461-2, "Low Voltage, 45MHz, Rail-to-Rail Output Operational Amplifiers with Shutdown Option, DBV0005A (SOT-23-5)", Manufacturer="Texas Instruments", Operating Temperature Range="-40 to 85 C", Rating=Catalog
U202: library part CMP-0750220-2, "INA293 High-Voltage, High Bandwidth, Unidirectional, 110-V Common-Mode, Current-Sense Amplifier, DBV0005A (SOT-23-5)", Alternate Manufacturer="Texas Instruments", Alternate PartNumber=INA293B3IDBVT
U203 U204: "Capacitor-Free, 150-mA, Low-Dropout Regulator with Foldback Current Limit for Portable Devices, DBV0005A", Alternate Manufacturer="Texas Instruments"

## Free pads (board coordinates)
  round 196.85 hole 118.11: 1(120,150) 1(236.22,3897.64) 1(4492.13,3673.23) 1(5860,160)
  round 0 hole 30 slot 110 at 90 deg unplated: 1(1068.74,3212.73) 1(1068.74,3811.16) 1(1193.74,3212.73) 1(1193.74,3811.16) 1(2261.74,3811.16) 1(2267.74,3214.16) 1(2381.89,3811.02) 1(2382.74,3214.16)
  rect 25x40 hole 10 copper offset 0,10: 1(1109.65,3267.61) 1(1109.65,3866.04) 1(1152.7,3267.61) 1(1152.7,3866.04) 1(2300.65,3866.04) 1(2306.65,3269.04) 1(2343.7,3865.04) 1(2349.7,3268.04)
  rect 25x40 hole 10 copper offset 0,-10: 1(1109.78,3156.85) 1(1109.78,3755.28) 1(1152.84,3156.85) 1(1152.84,3755.28) 1(2300.78,3755.28) 1(2306.78,3158.28) 1(2343.84,3754.28) 1(2349.84,3157.28)
  rect 118.11x78.74 hole 110 square unplated: 1(1129.74,3212.73) 1(1129.74,3811.16)
  oval 50x177.17 hole 30 slot 157.48 at 90 deg: 1(1250.74,3211.16) 1(1251.74,3211.73) 1(1251.74,3810.16) 1(1388.74,3211.16) 1(1389.74,3211.73) 1(1389.74,3810.16) 1(1475.74,3211.16) 1(1475.74,3808.16) 1(1618.74,3212.16) 1(1618.74,3809.16) 1(1823.74,3211.16) 1(1823.74,3808.16) 1(1978.74,3211.16) 1(1978.74,3808.16)
  rect 157.48x78.74 hole 157.48 square unplated: 1(1319.71,3210.57) 1(1319.71,3211.15) 1(1319.71,3809.57) 1(1546.74,3809.16)
  oval 187.01x50 hole 30 slot 167.32 at 0 deg: 1(1319.74,3278.16) 1(1320.74,3147.16) 1(1320.74,3278.73) 1(1320.74,3877.16) 1(1321.74,3147.73) 1(1321.74,3746.16) 1(1544.74,3278.16) 1(1544.74,3875.16) 1(1545.74,3147.16) 1(1545.74,3744.16) 1(1900.74,3277.16) 1(1901.74,3146.16) 1(1902.74,3874.16) 1(1903.74,3743.16)
  rect 167.32x78.74 hole 157.48 square unplated: 1(1546.74,3212.16) 1(1902.74,3211.16) 1(1902.74,3808.16)
  rect 137.8x78.74 hole 110 square unplated: 1(2324.74,3214.16) 1(2324.74,3811.16)
  rect 179x118.11 hole 118.11 square unplated: 1(2712.32,1610)
  rect 179x118.11 hole 120 square unplated: 1(3145.39,1350)
  round 60 hole 30: 1(4022.28,636.06) 1(4062.99,712.6) 1(4122.05,657.48) 1(4192.91,700.79) 1(4299.21,633.86) 1(4370,640)
  round 60 hole 36: 1(4133.86,177.17) 2(4133.86,98.43)
  rrect2% 161.42x456.69 hole 137.8 slot 433.07 at 90 deg: 1(4243.78,1770.28) 1(4334.33,2671.85)
  round 393.7 hole 214.57: 1(4944.88,3470.75) 1(4944.88,3903.82)
  rect 118.11x374.02 hole 78.74 slot 334.65 at 90 deg: 1(5659.21,2992.17) 1(5659.21,3937.05) 1(5828.5,2992.17) 1(5828.5,3937.05) 1(5997.8,2992.17) 1(5997.8,3937.05)

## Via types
v1: diameter 20, hole 10, Top Layer to Bottom Layer, 409 vias
v2: diameter 19.68, hole 7.87, Top Layer to Bottom Layer, 7 vias
v3: diameter 24, hole 8, Top Layer to Bottom Layer, tented both sides, 1 vias

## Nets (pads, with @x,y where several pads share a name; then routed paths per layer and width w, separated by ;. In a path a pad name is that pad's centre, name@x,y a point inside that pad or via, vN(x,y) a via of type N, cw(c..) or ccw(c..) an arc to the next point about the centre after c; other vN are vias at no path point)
3V3s: C206.1 C217.1 R213.1 R215.2 U200.5 U203.5 | length 2803.1
  Top Layer w20: U200.5@4511.81,86.61 v1(4535.43,86.61) ; 4519.69,62.99 R215.2@4562.99,62.99
  Top Layer w25: v1(3933.07,188.98) 3972.44,188.98 3980.31,196.85 C217.1@4023.62,196.85 ; C206.1@4511.81,35.43 U200.5@4511.81,86.61
  Signal Layer 3 w20: v1(3444.88,1177.17) 3456.69,1165.35 3456.69,1047.69 3694.48,809.9 4209.78,809.9 4240.16,779.53 4240.16,681.1 4227.23,668.17 4227.23,508.99 4535.43,200.79 v1(4535.43,86.61)
  Bottom Layer w20: v1(3444.88,1177.17) R213.1@3444.88,1216.54
  Bottom Layer w25: v1(3933.07,188.98) 4043.31,188.98 4082.68,228.35 4181.1,228.35 4346.46,62.99 4511.81,62.99 v1(4535.43,86.61)
3V3sa: C208.1 pad.1@2300.78,3755.28 pad.1@2306.78,3158.28 R236.2 U204.5 | length 1144.2
  Bottom Layer w20: pad.1@2299.21,3133.86 2251.97,3133.86 2232.28,3153.54 2232.28,3291.34 2259.84,3318.9 2413.39,3318.9 2460.63,3366.14 2460.63,3578.74 ; v1(2300.78,3735.16) 2300.78,3659.85 2381.89,3578.74 2460.63,3578.74 ; R236.2@2559.06,3673.23 2559.06,3582.68 2555.12,3578.74 2460.63,3578.74
  other v1: 2306.78,3138.16
5Vp: 5Vp.1 C124.1 L103.2 pad.1@1109.78,3156.85 pad.1@1109.78,3755.28 R120.2 U101.6 | length 3025
  Top Layer w20: R120.2@1291.38,1610 1291.38,1528.62 5Vp.1@1325,1495
  Signal Layer 2 w25: pad.1@1106.3,3736.22 1027.56,3657.48 1027.56,3102.36 1047.24,3082.68 1110.24,3082.68 pad.1@1110.24,3133.86
  Signal Layer 3 w20: 5Vp.1@1335,1485 5Vp.1@1335,1492.13
  Signal Layer 3 w25: v1(1109.78,3136.73) 1109.78,2370.53 1405.51,2074.8 1405.51,1996.06 1334.65,1925.2 5Vp.1@1334.65,1492.13
  Bottom Layer w10: L103.2@1335,1670 1355.16,1690.16 U101.6@1392.6,1690.16
  Bottom Layer w25: L103.2@1280,1658.66 1321.34,1658.66 1345,1635 C124.1@1345,1595
  Bottom Layer w50: 5Vp.1@1330,1485 1350,1505 C124.1@1350,1580
  other v1: 1109.78,3735.16
5Vs: 5Vs.1 C211.2 C216.1 C218.1 C220.1 J102.2 J102.4 J200.84 J200.98 J200.112 L200.2 R230.2 R236.1 U201.6 U202.3 U203.1 U203.3 U204.1 U204.3 | length 14474.4
  Top Layer w10: U201.6@2294.57,414.09 L200.2@2357.48,414.09
  Top Layer w20: v1(3031.5,240.16) 3037.68,246.34 J200.112@3037.68,349.53 ; v1(3255.91,240.16) 3258.15,242.4 J200.98@3258.15,349.53 ; v1(3476.38,240.16) 3478.62,242.4 J200.84@3478.62,349.53 ; C218.1@3858.27,55.12 v1(3858.27,82.68) 3858.27,94.49 3822.57,130.19 3822.57,169.02 3840.55,187.01 U203.1@3859.25,187.01 ; C218.1@3859.25,56.1 U203.3@3859.25,112.2 ; v1@4863.19,62.01 C211.2@4877.95,47.24 ; v1@4863.19,70.87 U202.3@4863.19,100.39
  Top Layer w100: 5Vs.1@2370,165 2370,320.31
  Signal Layer 2 w29.53: J102.4@2015.75,1263.78 1929.13,1263.78 1921.26,1255.91 1921.26,1153.54 2422.17,652.64 v1(2422.17,403.94) 2668.94,403.94 2730,465 2780,465 ; 2780,464.75 2780.12,464.75 2807.6,437.28 3690,437.28 3691,438.28 3798.43,438.28 3904.24,544.09 3904.24,560.82 3923.44,580.01 3923.68,580.01 3948.67,605 3948.67,724.26 3972.44,748.03 4119.41,895 v1(4165,895) 4461.33,895 4554.1,987.76 5133.44,987.76 5461.05,1315.38 5516.01,1315.38 5562.01,1361.38 v1@5562.01,1732.28
  Signal Layer 3 w20: v1(2422.17,403.94) 2586.1,240 2690,240 ; 2690,240.16 v1(3031.5,240.16) v1(3255.91,240.16) v1(3476.38,240.16)
  Signal Layer 3 w29.53: v1(2409.02,304.21) 2475,238.23 2475,145 2520,100 3400,100 3415,115 ; v1(2767.72,3484.25) 2889.76,3362.2 4429.13,3362.2 4629.92,3161.42 5094.49,3161.42 5539.37,2716.54 5633.86,2716.54 5747.53,2602.87 5747.53,1912.53 5567.28,1732.28 v1(5562.99,1732.28) ; 3414.61,115.39 3425.2,125.98 3814.96,125.98 v1(3858.27,82.68) 3905.51,35.43 4826.77,35.43 v1(4862.2,70.87)
  Bottom Layer w20: 2672.24,3586.61 R236.1@2672.24,3648.62
  Bottom Layer w29.53: R230.2@2369.65,335.71 2377.52,335.71 v1(2409.02,304.21) ; 2665.35,3484.25 v1(2767.72,3484.25) 2767.72,3570.87 2759.84,3578.74 U204.1@2669.29,3578.74
12Vp: 12Vp.1 C123.1 C125.1 pad.1@1152.7,3267.61 pad.1@1152.7,3866.04 U101.2 U101.3 | length 3563.7
  Top Layer w50: 12Vp.1@1335,2015 1690,1660 1701.1,1660
  Signal Layer 3 w20: 1027.56,3338.58 1137.8,3338.58 1152.95,3323.43 v1(1152.95,3287.73) ; v1(1152.95,3886.16) 1152.95,3921.85 1141.73,3933.07 1086.61,3933.07 1023.62,3870.08 1023.62,2413.39 1335,2102.01 12Vp.1@1335,2015
  Bottom Layer w10: U101.3@1467.4,1690.16 C123.1@1529.84,1690.16 ; U101.2@1467.4,1709.84 1510.16,1709.84 C123.1@1520,1700
  Bottom Layer w50: C123.1@1540,1685 1580,1685 1601.93,1663.07 C125.1@1625,1663.07 1688.07,1663.07 1688.07,1556.93 1725,1520 1725,1355 ; 1615,1398.74 1718.74,1398.74
  other v1: 1590,1480 1635,1480
12Vs: 12Vs.1 C215.1 C219.1 J102.5 J102.11 U201.2 U201.3 | length 1540
  Top Layer w10: C215.1@2172.32,414.09 U201.3@2219.76,414.09 ; C215.1@2172.32,433.78 U201.2@2219.76,433.78
  Top Layer w25: 1984.25,338.58 2023.62,377.95 ; 2070.87,1145.67 2072.05,1144.49 ; 2072.05,422.44 2072.05,1144.49 ; J102.5@2072.05,1210 2072.05,1144.49 ; J102.11@2222.05,1210 2222.05,1170.87 2192.91,1141.73 2074.8,1141.73 2072.05,1144.49
  Top Layer w50: 12Vs.1@1964.13,166.42 2011.38,213.66 C219.1@2011.38,268.78 2011.38,355.39 2090.12,434.13 C215.1@2160.98,434.13
  Signal Layer 2 w25: 12Vs.1@1970,170 12Vs.1@1975,165
54V1: C112.2 Q100.1 Q100.2 Q100.3 Q101.1 Q101.2 Q101.3 Q102.1 Q102.2 Q102.3 Q103.1 Q103.2 Q103.3 Q104.1 Q104.2 Q104.3 Q105.1 Q105.2 Q105.3 Q106.1 Q106.2 Q106.3 Q107.1 Q107.2 Q107.3 R100.2 R101.2 R105.2 R106.2 R223.1 R229.2 U100.2 U100.3 | length 4766.8
  Top Layer w20: R229.2@4606.3,759.84 4615.16,759.84 4635,740 4783.31,740 5031.5,988.19 C112.2@5570.87,988.19 ; R223.1@5141.73,169.29 v1(5204.72,169.29) ; C112.2@5594.49,992.13 5602.36,1000 v1(5602.36,1027.56)
  Signal Layer 3 w20: v1(5118.11,2200.79) 5177.17,2141.73 5177.17,1769.39 5230.02,1716.54 5230.02,1482.2 5401.57,1310.65 5401.57,477.01 5204.72,280.15 v1(5204.72,169.29) ; v1(5267.72,2204.72) 5284.02,2188.42 5284.02,1504.56 5464.57,1324.02 5464.57,1261.03 5602.36,1123.23 v1(5602.36,1027.56)
  Bottom Layer w20: 5602.36,984.25 v1(5602.36,1027.56)
  other v1: 5204.72,1787.4 5204.72,1818.9 5204.72,1850.39 5204.72,1881.89 5204.72,1913.39 5204.72,1944.88 5204.72,1976.38 5204.72,2007.87 5204.72,2039.37 5204.72,2074.8 5204.72,2106.3 5204.72,2137.8 5204.72,2169.29 5204.72,2200.79 5204.72,2232.28 5204.72,2263.78 5204.72,2295.28 5204.72,2326.77 5204.72,2358.27 5204.72,2389.76 5204.72,2421.26 5204.72,2452.76 5204.72,2484.25 5204.72,2515.75 5204.72,2547.24 5204.72,2578.74 5204.72,2610.24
